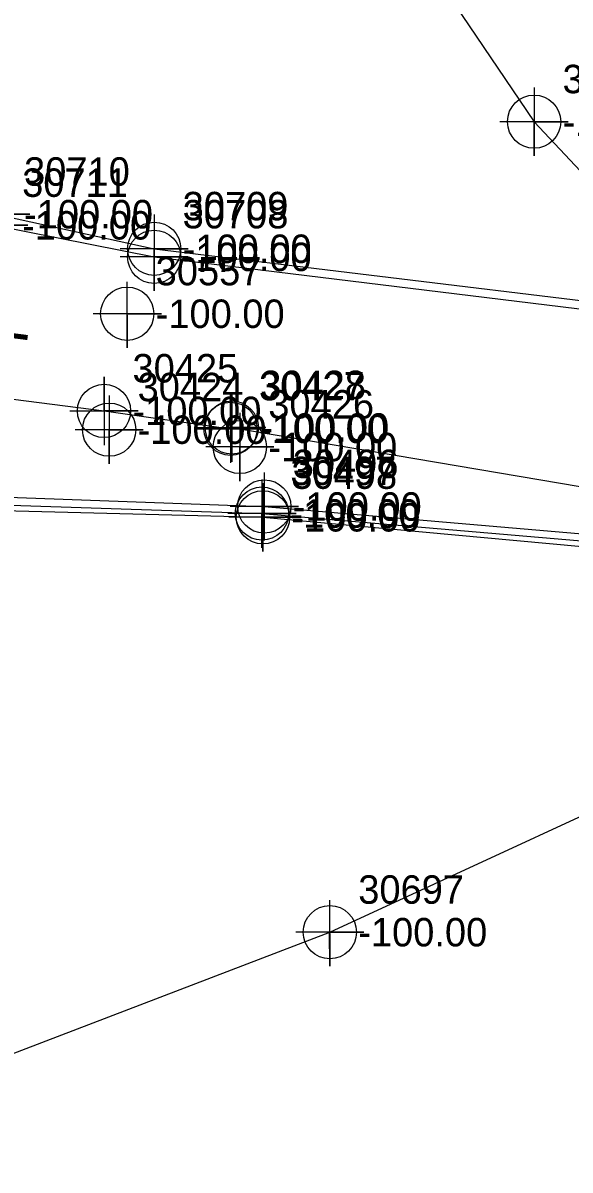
# Model space of a CAD drawing. Extents: x 2083698 to 2094313, y 743246 to 752873.
# Drawn here: x 2090186.6 to 2090234.7, y 744662.6 to 744763.4 of the extents above; entities that cross this region are included whole.
import ezdxf

# ---------------------------------------------------------------- set-up
doc = ezdxf.new("R2010")
doc.units = 0
for name, color, linetype in [('COGO Default Chain', 7, 'Continuous'), ('COGO Default Curve', 7, 'Continuous'), ('COGO Default Point Number', 7, 'Continuous'), ('Default Symbol CELL', 7, 'Continuous'), ('Default Symbol Cogo Number', 7, 'Continuous'), ('Exist Property Iron Pin Leader', 7, 'Continuous'), ('Exist Property Iron Pin Text', 7, 'Continuous'), ('Exist Property Line', 7, 'Continuous'), ('Exist Property Line Leader', 7, 'Continuous'), ('Exist Property Monument Text', 7, 'Continuous'), ('Exist Right of Way Line', 7, 'Continuous'), ('Exist Right of Way Line Leader', 7, 'Continuous'), ('Exist Right of Way Line Text', 7, 'Continuous'), ('Exist Utilities Gas UG Line SUE LOS B', 7, 'Continuous'), ('Exist Utilities Gas UG Line SUE LOS B Text', 7, 'Continuous'), ('Exist Utilities Power UG Cable SUE LOS B', 7, 'Continuous'), ('Exist Utilities Telephone UG Conduit SUE LOS B', 7, 'Continuous'), ('Exist Utilities TV UG Cable SUE LOS B', 7, 'Continuous'), ('Old_Level_20', 7, 'Continuous'), ('Scratch_Level_2', 7, 'Continuous')]:
    doc.layers.add(name, color=color, linetype=linetype)

msp = doc.modelspace()

# ---------------------------------------------------------------- linework, layer by layer
at = {"layer": 'COGO Default Curve'}
for points in [[(2090190.7, 744729.31), (2090196.7, 744729.31), (2090193.7, 744729.31), (2090193.7, 744732.31), (2090193.7, 744726.31)], [(2090201.82, 744727.74), (2090207.82, 744727.74), (2090204.82, 744727.74), (2090204.82, 744730.74), (2090204.82, 744724.74)], [(2090201.93, 744727.85), (2090207.93, 744727.85), (2090204.93, 744727.85), (2090204.93, 744730.85), (2090204.93, 744724.85)]]:
    msp.add_lwpolyline(points, dxfattribs=at)
for centre in [(2090193.7, 744729.31), (2090204.82, 744727.74), (2090204.93, 744727.85)]:
    msp.add_circle(centre, 2.34, dxfattribs=at)
at = {"layer": 'COGO Default Point Number'}
for points in [[(2090194.15, 744730.66), (2090194.15, 744724.66), (2090194.15, 744727.66), (2090197.15, 744727.66), (2090191.15, 744727.66)], [(2090205.64, 744729.14), (2090205.64, 744723.14), (2090205.64, 744726.14), (2090208.64, 744726.14), (2090202.64, 744726.14)]]:
    msp.add_lwpolyline(points, dxfattribs=at)
for centre in [(2090194.15, 744727.66), (2090205.64, 744726.14)]:
    msp.add_circle(centre, 2.34, dxfattribs=at)
at = {"layer": 'Exist Property Iron Pin Text'}
msp.add_lwpolyline([(2090231.51, 744757.73), (2090231.51, 744751.73), (2090231.51, 744754.73), (2090234.51, 744754.73), (2090228.51, 744754.73)], dxfattribs=at)
msp.add_circle((2090231.51, 744754.73), 2.34, dxfattribs=at)
at = {"layer": 'Exist Property Line Leader'}
for points in [[(2090184.17, 744749.6), (2090184.17, 744743.6), (2090184.17, 744746.6), (2090187.17, 744746.6), (2090181.17, 744746.6)], [(2090184, 744748.62), (2090184, 744742.62), (2090184, 744745.62), (2090187, 744745.62), (2090181, 744745.62)], [(2090198.11, 744746.56), (2090198.11, 744740.56), (2090198.11, 744743.56), (2090201.11, 744743.56), (2090195.11, 744743.56)], [(2090198.11, 744745.85), (2090198.11, 744739.85), (2090198.11, 744742.85), (2090201.11, 744742.85), (2090195.11, 744742.85)], [(2090207.79, 744723.91), (2090207.79, 744717.91), (2090207.79, 744720.91), (2090210.79, 744720.91), (2090204.79, 744720.91)], [(2090207.58, 744723.29), (2090207.58, 744717.29), (2090207.58, 744720.29), (2090210.58, 744720.29), (2090204.58, 744720.29)], [(2090207.67, 744722.96), (2090207.67, 744716.96), (2090207.67, 744719.96), (2090210.67, 744719.96), (2090204.67, 744719.96)]]:
    msp.add_lwpolyline(points, dxfattribs=at)
for centre in [(2090198.11, 744743.56), (2090198.11, 744742.85), (2090207.58, 744720.29), (2090207.79, 744720.91), (2090207.67, 744719.96)]:
    msp.add_circle(centre, 2.34, dxfattribs=at)
at = {"layer": 'Exist Right of Way Line Text'}
for points in [[(2090195.71, 744740.66), (2090195.74, 744734.85), (2090195.73, 744737.85), (2090198.74, 744737.85), (2090192.74, 744737.85)], [(2090213.52, 744686.32), (2090213.55, 744680.5), (2090213.53, 744683.5), (2090216.55, 744683.5), (2090210.55, 744683.5)]]:
    msp.add_lwpolyline(points, dxfattribs=at)
for centre in [(2090195.74, 744737.85), (2090213.55, 744683.5)]:
    msp.add_circle(centre, 2.34, dxfattribs=at)
at = {"layer": 'Exist Utilities Gas UG Line SUE LOS B'}
msp.add_lwpolyline([(2090047.15, 744748.21), (2090068.01, 744744.82), (2090107.48, 744739.55), (2090148.02, 744734.49), (2090170.59, 744732.29), (2090193.7, 744729.31), (2090204.82, 744727.74), (2090204.93, 744727.85), (2090248.2, 744720.53), (2090269.93, 744716.3), (2090289.96, 744713.23), (2090336.35, 744705.98), (2090374.71, 744698.49), (2090425.22, 744688.42), (2090470.85, 744676.5), (2090490.54, 744672.23), (2090531.88, 744663.02)], dxfattribs=at)
at = {"layer": 'Exist Utilities Power UG Cable SUE LOS B'}
msp.add_lwpolyline([(2090213.86, 744782.59), (2090213.69, 744781.05), (2090231.51, 744754.73), (2090247.29, 744737.92), (2090254.23, 744731.28), (2090264.85, 744725.3), (2090278.14, 744720.59), (2090299.81, 744717.33), (2090328.01, 744711.05), (2090354.61, 744706.07), (2090367.22, 744701.66), (2090394.7, 744690.95)], dxfattribs=at)
at = {"layer": 'Exist Utilities Telephone UG Conduit SUE LOS B'}
msp.add_lwpolyline([(2090084.61, 744620.75), (2090090.44, 744625.41), (2090099.6, 744631.4), (2090112.39, 744635.81), (2090122.72, 744643.08), (2090145.14, 744657.13), (2090168.77, 744666.37), (2090213.55, 744683.5), (2090249.98, 744700.33), (2090263.01, 744710.66), (2090276.23, 744725.26), (2090278.08, 744728.76)], dxfattribs=at)
at = {"layer": 'Exist Utilities TV UG Cable SUE LOS B'}
for points in [[(2089879.75, 744760.36), (2089901.98, 744763.32), (2089916.43, 744761.67), (2089931.56, 744764.12), (2089956.14, 744773.33), (2089967.61, 744777.01), (2089971.96, 744776.87), (2089978.23, 744774.08), (2089992.16, 744773.09), (2090002.24, 744772.26), (2090017.08, 744773.33), (2090046.64, 744770.39), (2090070.6, 744764.9), (2090114.8, 744754.51), (2090128.8, 744753.2), (2090131.09, 744754.17), (2090156.49, 744752.17), (2090184, 744745.62), (2090198.11, 744742.85), (2090237.91, 744737.98), (2090240.89, 744737.37), (2090257.27, 744724.27)], [(2089879.9, 744759.63), (2089902.06, 744761.97), (2089916.1, 744760.95), (2089931.79, 744763.27), (2089956.25, 744772.44), (2089967.49, 744776.52), (2089971.98, 744776.18), (2089977.92, 744773.59), (2089991.95, 744772.56), (2090002.24, 744771.77), (2090017.2, 744772.77), (2090046.69, 744769.85), (2090070.56, 744765.41), (2090115.09, 744755.14), (2090128.73, 744754.27), (2090131.27, 744754.96), (2090156.54, 744752.8), (2090184.17, 744746.6), (2090198.11, 744743.56), (2090237.8, 744738.76), (2090241.01, 744737.83), (2090257.47, 744724.69)], [(2089730.43, 744762.01), (2089790.68, 744757.7), (2089834.81, 744757.41), (2089855.99, 744754.81), (2089868.12, 744753.96), (2089881.87, 744756.48), (2089897.49, 744753.99), (2089909.79, 744753), (2089960.17, 744742.92), (2089977.42, 744737.63), (2090000.44, 744733.89), (2090043.67, 744732.64), (2090043.7, 744732.62), (2090070.4, 744729.05), (2090116.75, 744725.04), (2090148.32, 744723.08), (2090207.79, 744720.91), (2090260.99, 744716.35), (2090285.16, 744715.19), (2090303.73, 744712.21)], [(2089730.34, 744760.93), (2089790.92, 744756.15), (2089834.9, 744755.74), (2089856.04, 744753.44), (2089868.17, 744752.66), (2089882, 744754.92), (2089897, 744752.39), (2089909.32, 744751.68), (2089959.25, 744741.89), (2089977.09, 744736.08), (2090000.07, 744732.19), (2090043.34, 744731.45), (2090070.55, 744727.33), (2090116.37, 744723.83), (2090148.24, 744721.49), (2090207.67, 744719.96), (2090260.95, 744715.07), (2090285.13, 744714.46), (2090285.21, 744713.98), (2090303.72, 744712.3)], [(2089730.43, 744761.5), (2089790.79, 744756.97), (2089834.91, 744756.53), (2089856.06, 744754.21), (2089868.05, 744753.48), (2089882, 744755.93), (2089897.29, 744753.36), (2089909.4, 744752.38), (2089959.72, 744742.47), (2089977.22, 744736.73), (2090000.15, 744733), (2090043.57, 744732.14), (2090070.4, 744728.46), (2090116.7, 744724.46), (2090148.41, 744722.27), (2090207.58, 744720.29), (2090261.01, 744715.72), (2090303.74, 744712.2)]]:
    msp.add_lwpolyline(points, dxfattribs=at)

# ---------------------------------------------------------------- texts
at = {"layer": 'COGO Default Chain'}
for p in [(2090196.2, 744728.06), (2090207.32, 744726.49), (2090207.43, 744726.6)]:
    msp.add_text('-100.00', height=2.5, dxfattribs=at).set_placement(p)
at = {"layer": 'Default Symbol CELL'}
for s, p in [('30710', (2090186.67, 744749.1)), ('30711', (2090186.5, 744748.12)), ('30709', (2090200.61, 744746.06)), ('30708', (2090200.61, 744745.35)), ('30496', (2090210.29, 744723.41)), ('30497', (2090210.08, 744722.79)), ('30498', (2090210.17, 744722.46))]:
    msp.add_text(s, height=2.5, dxfattribs=at).set_placement(p)
at = {"layer": 'Default Symbol Cogo Number'}
for p in [(2090186.67, 744745.35), (2090186.5, 744744.37), (2090200.61, 744742.31), (2090200.61, 744741.6), (2090210.08, 744719.04), (2090210.29, 744719.66), (2090210.17, 744718.71)]:
    msp.add_text('-100.00', height=2.5, dxfattribs=at).set_placement(p)
at = {"layer": 'Exist Property Iron Pin Leader'}
msp.add_text('30607', height=2.5, dxfattribs=at).set_placement((2090234.01, 744757.23))
at = {"layer": 'Exist Property Line'}
for p in [(2090196.65, 744726.41), (2090208.14, 744724.89)]:
    msp.add_text('-100.00', height=2.5, dxfattribs=at).set_placement(p)
at = {"layer": 'Exist Property Monument Text'}
msp.add_text('-100.00', height=2.5, dxfattribs=at).set_placement((2090234.01, 744753.48))
at = {"layer": 'Exist Right of Way Line'}
for s, p in [('30424', (2090196.65, 744730.16)), ('30426', (2090208.14, 744728.64))]:
    msp.add_text(s, height=2.5, dxfattribs=at).set_placement(p)
at = {"layer": 'Exist Right of Way Line Leader'}
for s, p in [('30557', (2090198.24, 744740.35)), ('30697', (2090216.05, 744686))]:
    msp.add_text(s, height=2.5, dxfattribs=at).set_placement(p)
at = {"layer": 'Exist Utilities Gas UG Line SUE LOS B Text'}
msp.add_text('PSNC,Unk. S/T', height=4, rotation=352.6444, dxfattribs=at).set_placement((2090149.77, 744736.75))
at = {"layer": 'Old_Level_20'}
for s, p in [('30425', (2090196.2, 744731.81)), ('30427', (2090207.32, 744730.24)), ('30428', (2090207.43, 744730.35))]:
    msp.add_text(s, height=2.5, dxfattribs=at).set_placement(p)
at = {"layer": 'Scratch_Level_2'}
for p in [(2090198.24, 744736.6), (2090216.05, 744682.25)]:
    msp.add_text('-100.00', height=2.5, dxfattribs=at).set_placement(p)

doc.saveas('drawing.dxf')
